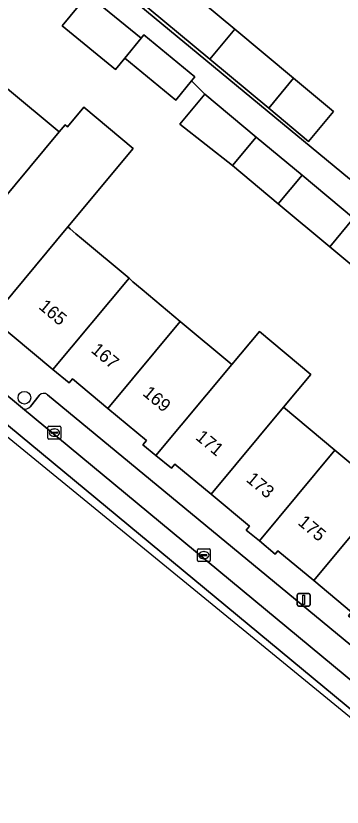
# Model space of a CAD drawing. Extents: x 162073 to 163043, y 381818 to 382561.
# Drawn here: x 162451.7 to 162477.1, y 381850 to 381911.5 of the extents above; entities that cross this region are included whole.
import ezdxf

# ---------------------------------------------------------------- set-up
doc = ezdxf.new("R2010")
doc.units = 0
for name, color, linetype in [('IMGEO_Boom', 7, 'Continuous'), ('IMGEO_Erf', 7, 'Continuous'), ('IMGEO_Kolk', 7, 'Continuous'), ('IMGEO_Lichtmast', 7, 'Continuous'), ('IMGEO_Pand', 7, 'Continuous'), ('IMGEO_Pand_nummerreeks', 7, 'Continuous'), ('IMGEO_Parkeervlak_open', 7, 'Continuous'), ('IMGEO_Rijbaan_lokaal_gesloten', 7, 'Continuous'), ('IMGEO_Rijbaan_lokaal_open', 7, 'Continuous'), ('IMGEO_Voetpad_open', 7, 'Continuous')]:
    doc.layers.add(name, color=color, linetype=linetype)

msp = doc.modelspace()

# ---------------------------------------------------------------- linework, layer by layer
at = {"layer": 'IMGEO_Boom'}
msp.add_circle((162452.39, 381881.818), 0.489, dxfattribs=at)
at = {"layer": 'IMGEO_Erf'}
for points in [[(162462.808, 381915.405), (162468.748, 381910.459), (162473.32, 381906.653), (162476.42, 381904.073), (162474.484, 381901.747), (162471.384, 381904.327), (162466.812, 381908.133), (162460.871, 381913.079)], [(162480.473, 381889.94), (162476.133, 381893.553), (162472.125, 381896.889), (162468.555, 381899.861), (162464.478, 381903.085), (162466.409, 381905.405), (162465.384, 381906.441), (162464.168, 381904.954), (162460.183, 381908.213), (162459.469, 381907.341), (162455.331, 381910.722), (162457.324, 381913.159)], [(162460.699, 381912.872), (162477.652, 381898.823)], [(162451.065, 381905.836), (162455.089, 381902.482), (162455.554, 381903.04), (162455.743, 381902.883), (162457.002, 381904.394), (162460.841, 381901.198), (162455.756, 381895.097), (162455.949, 381894.936), (162456.394, 381894.565), (162456.838, 381894.195), (162460.527, 381891.12), (162460.821, 381890.823), (162461.541, 381890.223), (162464.509, 381887.752), (162468.518, 381884.415), (162470.654, 381886.978), (162474.661, 381883.637), (162472.527, 381881.077), (162476.535, 381877.739), (162480.543, 381874.403)]]:
    msp.add_lwpolyline(points, dxfattribs=at)
at = {"layer": 'IMGEO_Kolk'}
for p, q in [((162454.218, 381878.684), (162454.218, 381879.536)), ((162454.293, 381879.61), (162455.145, 381879.61)), ((162454.477, 381879.104), (162454.477, 381879.116)), ((162454.52, 381879.153), (162454.918, 381879.153)), ((162454.706, 381879.39), (162454.731, 381879.39)), ((162454.961, 381879.116), (162454.961, 381879.104)), ((162455.219, 381879.536), (162455.219, 381878.684)), ((162455.145, 381878.61), (162454.293, 381878.61)), ((162454.915, 381879.067), (162454.517, 381879.067)), ((162454.729, 381878.83), (162454.704, 381878.83)), ((162465.838, 381869.158), (162465.838, 381870.01)), ((162465.913, 381870.084), (162466.765, 381870.084)), ((162466.326, 381869.864), (162466.351, 381869.864)), ((162466.839, 381870.01), (162466.839, 381869.158)), ((162466.097, 381869.578), (162466.097, 381869.59)), ((162466.535, 381869.541), (162466.137, 381869.541)), ((162466.14, 381869.627), (162466.538, 381869.627)), ((162466.349, 381869.304), (162466.324, 381869.304)), ((162466.581, 381869.59), (162466.581, 381869.578)), ((162466.765, 381869.084), (162465.913, 381869.084))]:
    msp.add_line(p, q, dxfattribs=at)
for points in [[(162454.218, 381878.684), (162454.218, 381879.536)], [(162454.293, 381879.61), (162455.145, 381879.61)], [(162455.219, 381879.536), (162455.219, 381878.684)], [(162455.145, 381878.61), (162454.293, 381878.61)], [(162465.838, 381869.158), (162465.838, 381870.01)], [(162465.913, 381870.084), (162466.765, 381870.084)], [(162466.839, 381870.01), (162466.839, 381869.158)], [(162466.765, 381869.084), (162465.913, 381869.084)]]:
    msp.add_lwpolyline(points, dxfattribs=at)
for centre, radius, start, end in [((162454.295, 381879.534), 0.0765, 91.55205, 178.44795), ((162454.295, 381879.534), 0.0765, 91.55205, 178.44795), ((162454.517, 381879.113), 0.0403, 85.87752, 175.75265), ((162454.514, 381879.103), 0.0366, 178.93798, 274.71019), ((162454.918, 381879.11), 0.043, 264.86636, 352.45326), ((162454.922, 381879.115), 0.0386, 1.73085, 96.63898), ((162455.143, 381879.534), 0.0765, 1.55205, 88.44795), ((162455.143, 381879.534), 0.0765, 1.55205, 88.44795), ((162454.295, 381878.686), 0.0765, 181.55205, 268.44795), ((162454.295, 381878.686), 0.0765, 181.55205, 268.44795), ((162455.143, 381878.686), 0.0765, 271.55205, 358.44795), ((162455.143, 381878.686), 0.0765, 271.55205, 358.44795), ((162465.915, 381870.008), 0.0765, 91.55205, 178.44795), ((162465.915, 381870.008), 0.0765, 91.55205, 178.44795), ((162466.763, 381870.008), 0.0765, 1.55205, 88.44795), ((162466.763, 381870.008), 0.0765, 1.55205, 88.44795), ((162466.137, 381869.587), 0.0403, 85.87752, 175.75265), ((162466.134, 381869.577), 0.0366, 178.93798, 274.71019), ((162466.538, 381869.584), 0.043, 264.86636, 352.45326), ((162466.542, 381869.589), 0.0386, 1.73085, 96.63898), ((162465.915, 381869.16), 0.0765, 181.55205, 268.44795), ((162465.915, 381869.16), 0.0765, 181.55205, 268.44795), ((162466.763, 381869.16), 0.0765, 271.55205, 358.44795), ((162466.763, 381869.16), 0.0765, 271.55205, 358.44795)]:
    msp.add_arc(centre, radius, start, end, dxfattribs=at)
for centre, major_axis, ratio, start_param, end_param in [((162454.705, 381879.11), (-0.387, 0.002), 0.722429, 4.712389, 7.853982), ((162454.73, 381879.11), (-0.39, 0.002), 0.717154, 1.570796, 4.712389), ((162466.325, 381869.584), (-0.387, 0.002), 0.722429, 4.712389, 7.853982), ((162466.35, 381869.584), (-0.39, 0.002), 0.717154, 1.570796, 4.712389)]:
    msp.add_ellipse(centre, major_axis=major_axis, ratio=ratio, start_param=start_param, end_param=end_param, dxfattribs=at)
at = {"layer": 'IMGEO_Lichtmast'}
for p, q in [((162473.604, 381865.711), (162473.604, 381866.511)), ((162473.604, 381866.511), (162473.604, 381865.711)), ((162473.704, 381866.611), (162474.494, 381866.611)), ((162474.494, 381866.611), (162473.704, 381866.611)), ((162474.594, 381866.511), (162474.594, 381865.711)), ((162474.594, 381865.711), (162474.594, 381866.511)), ((162474.494, 381865.611), (162473.704, 381865.611)), ((162473.704, 381865.611), (162474.494, 381865.611))]:
    msp.add_line(p, q, dxfattribs=at)
msp.add_lwpolyline([(162474.024, 381866.486), (162474.174, 381866.486), (162474.174, 381865.736), (162474.024, 381865.736), (162474.024, 381866.486)], dxfattribs=at)
for centre, start, end in [((162473.704, 381866.511), 90, 180), ((162473.704, 381866.511), 90, 180), ((162474.494, 381866.511), 0, 90), ((162474.494, 381866.511), 360, 90), ((162473.704, 381865.711), 180, 270), ((162473.704, 381865.711), 180, 270), ((162474.494, 381865.711), 270, 0), ((162474.494, 381865.711), 270, 0)]:
    msp.add_arc(centre, 0.1, start, end, dxfattribs=at)
at = {"layer": 'IMGEO_Pand'}
for points in [[(162462.808, 381915.405), (162460.871, 381913.079), (162466.812, 381908.133), (162468.748, 381910.459)], [(162457.324, 381913.159), (162455.331, 381910.722), (162459.469, 381907.341), (162460.183, 381908.213), (162461.461, 381909.776)], [(162468.748, 381910.459), (162466.812, 381908.133), (162471.384, 381904.327), (162473.32, 381906.653)], [(162461.664, 381910.024), (162461.461, 381909.776), (162460.183, 381908.213), (162464.168, 381904.954), (162465.384, 381906.441), (162465.649, 381906.765)], [(162473.32, 381906.653), (162471.384, 381904.327), (162474.484, 381901.747), (162476.42, 381904.073)], [(162455.089, 381902.482), (162451.065, 381905.836), (162447.666, 381901.759), (162442.033, 381895.001), (162445.037, 381892.5), (162444.783, 381892.195), (162445.805, 381891.344)], [(162468.555, 381899.861), (162470.403, 381902.081), (162466.409, 381905.405), (162464.478, 381903.085)], [(162460.841, 381901.198), (162457.002, 381904.394), (162455.743, 381902.883), (162455.554, 381903.04), (162455.089, 381902.482), (162445.805, 381891.344), (162449.832, 381887.991), (162455.756, 381895.097)], [(162473.974, 381899.108), (162470.403, 381902.081), (162468.555, 381899.861), (162472.125, 381896.889)], [(162473.974, 381899.108), (162472.125, 381896.889), (162476.133, 381893.553), (162477.982, 381895.771)], [(162477.982, 381895.771), (162476.133, 381893.553), (162480.473, 381889.94), (162482.321, 381892.159)], [(162455.756, 381895.097), (162449.832, 381887.991), (162454.606, 381884.017), (162460.527, 381891.12), (162456.838, 381894.195), (162456.394, 381894.565), (162455.949, 381894.936)], [(162464.509, 381887.752), (162461.541, 381890.223), (162460.821, 381890.823), (162460.527, 381891.12), (162454.606, 381884.017), (162455.865, 381882.969), (162456.123, 381883.279), (162458.873, 381880.99)], [(162462.614, 381877.332), (162468.518, 381884.415), (162464.509, 381887.752), (162458.873, 381880.99), (162461.873, 381878.492), (162461.606, 381878.171)], [(162462.614, 381877.332), (162463.815, 381876.333), (162464.087, 381876.66), (162466.896, 381874.322), (162472.527, 381881.077), (162474.661, 381883.637), (162470.654, 381886.978), (162468.518, 381884.415)], [(162470.656, 381870.686), (162476.535, 381877.739), (162472.527, 381881.077), (162466.896, 381874.322), (162469.88, 381871.837), (162469.631, 381871.539)], [(162470.656, 381870.686), (162471.877, 381869.669), (162472.093, 381869.928), (162474.879, 381867.608), (162480.543, 381874.403), (162476.535, 381877.739)], [(162486.563, 381873.478), (162484.761, 381874.978), (162482.751, 381872.565), (162480.543, 381874.403), (162474.879, 381867.608), (162477.821, 381865.158), (162477.584, 381864.873), (162478.65, 381863.985), (162484.552, 381871.065)]]:
    msp.add_lwpolyline(points, close=True, dxfattribs=at)
at = {"layer": 'IMGEO_Parkeervlak_open'}
for points in [[(162453.541, 381882.004), (162452.853, 381881.148)], [(162491.06, 381849.505), (162490.798, 381851.341), (162490.52, 381852.068), (162454.194, 381882.053)], [(162452.242, 381880.997), (162491.693, 381848.348)]]:
    msp.add_lwpolyline(points, dxfattribs=at)
for centre, radius, start, end in [((162453.892, 381881.696), 0.467, 49.80289, 138.77978), ((162452.467, 381881.4), 0.461, 240.85077, 326.91261)]:
    msp.add_arc(centre, radius, start, end, dxfattribs=at)
at = {"layer": 'IMGEO_Rijbaan_lokaal_gesloten'}
msp.add_lwpolyline([(162508.667, 381838.427), (162507.377, 381838.642), (162503.603, 381839.58), (162499.631, 381842.815), (162491.849, 381848.219), (162491.693, 381848.348), (162452.242, 381880.997), (162445.326, 381886.723), (162434, 381896.128), (162430.089, 381899.381), (162429.979, 381899.472), (162408.994, 381916.777), (162394.077, 381929.097), (162393.04, 381927.87), (162402.622, 381920.132), (162410.692, 381913.142), (162484.933, 381851.65), (162484.656, 381851.328), (162491.247, 381845.941), (162505.446, 381835.561), (162507.867, 381833.252)], dxfattribs=at)
at = {"layer": 'IMGEO_Rijbaan_lokaal_open'}
msp.add_lwpolyline([(162410.692, 381913.142), (162438.538, 381889.024), (162471.681, 381861.933), (162484.656, 381851.328), (162484.933, 381851.65), (162410.692, 381913.142)], dxfattribs=at)
at = {"layer": 'IMGEO_Voetpad_open'}
for points in [[(162457.324, 381913.159), (162461.461, 381909.776), (162461.664, 381910.024), (162465.649, 381906.765), (162465.384, 381906.441), (162466.409, 381905.405), (162470.403, 381902.081), (162473.974, 381899.108), (162477.982, 381895.771)], [(162525.473, 381857.142), (162518.578, 381863.049), (162507.062, 381872.913), (162502.405, 381876.903), (162501.429, 381878.965), (162498.683, 381881.242), (162495.937, 381883.52), (162492.127, 381886.812), (162489.572, 381888.931), (162486.809, 381891.223), (162483.019, 381894.309), (162480.335, 381896.566), (162477.652, 381898.823), (162460.699, 381912.872)], [(162464.087, 381876.66), (162463.815, 381876.333), (162462.614, 381877.332), (162461.606, 381878.171), (162461.873, 381878.492), (162458.873, 381880.99), (162456.123, 381883.279), (162455.865, 381882.969), (162454.606, 381884.017), (162449.832, 381887.991)], [(162445.326, 381886.723), (162452.242, 381880.997)], [(162452.853, 381881.148), (162453.541, 381882.004)], [(162454.194, 381882.053), (162490.52, 381852.068), (162490.798, 381851.341), (162491.06, 381849.505)], [(162496.099, 381849.397), (162494.789, 381850.487), (162493.478, 381851.579), (162493.767, 381851.927), (162490.936, 381854.284), (162488.054, 381856.684), (162487.813, 381856.395), (162486.687, 381857.333), (162485.553, 381858.276), (162485.793, 381858.563), (162482.918, 381860.957), (162480.074, 381863.325), (162479.816, 381863.014), (162478.65, 381863.985), (162477.584, 381864.873), (162477.821, 381865.158), (162474.879, 381867.608), (162472.093, 381869.928), (162471.877, 381869.669), (162470.656, 381870.686), (162469.631, 381871.539), (162469.88, 381871.837), (162466.896, 381874.322), (162464.087, 381876.66)]]:
    msp.add_lwpolyline(points, dxfattribs=at)
for centre, radius, start, end in [((162453.892, 381881.696), 0.467, 49.80289, 138.77978), ((162452.467, 381881.4), 0.461, 240.85077, 326.91261)]:
    msp.add_arc(centre, radius, start, end, dxfattribs=at)

# ---------------------------------------------------------------- texts
at = {"layer": 'IMGEO_Pand_nummerreeks'}
for s, rotation, p in [('165', 320.12787, (162453.435, 381888.796)), ('167', 320.21381, (162457.498, 381885.412)), ('169', 320.21117, (162461.52, 381882.063)), ('171', 320.21117, (162465.629, 381878.641)), ('173', 320.21117, (162469.562, 381875.365)), ('175', 320.21117, (162473.584, 381872.016))]:
    msp.add_text(s, height=1, rotation=rotation, dxfattribs=at).set_placement(p)

doc.saveas('drawing.dxf')
